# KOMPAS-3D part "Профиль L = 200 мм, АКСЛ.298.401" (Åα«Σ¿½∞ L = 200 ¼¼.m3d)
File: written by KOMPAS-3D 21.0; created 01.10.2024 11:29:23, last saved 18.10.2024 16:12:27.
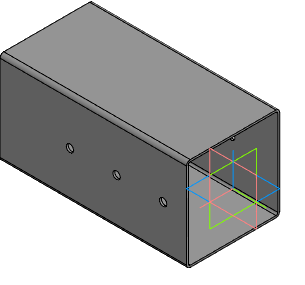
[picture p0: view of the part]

Document properties: Полное имя файла: C:\Users\Алексей Бочаров\YandexDisk\Соединения бруса\Соединения бруса\КВАТРО\Профиль L = 200 мм.m3d; Автор: Алексей Бочаров

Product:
- Part/product: Профиль L = 200 мм  | designation АКСЛ.298.401
    Масса: 1.210897
    Форматы листов документа: A2

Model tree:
1. Эскиз:1
2. Элемент выдавливания:1
     Расстояние 2 = 250
3. Эскиз:2  (with: Элемент выдавливания:1)
4. Элемент выдавливания:2
5. Эскиз:3  (with: Элемент выдавливания:1)
6. Элемент выдавливания:3  (with: Элемент выдавливания:1)
     Расстояние 2 = 2
7. Эскиз:4  (with: Элемент выдавливания:1)
8. Элемент выдавливания:4  (with: Элемент выдавливания:1)
     Расстояние 2 = 2
9. Эскиз:5  (with: Элемент выдавливания:1, Элемент выдавливания:2)
10. Элемент выдавливания:5

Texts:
  АКСЛ.298.401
